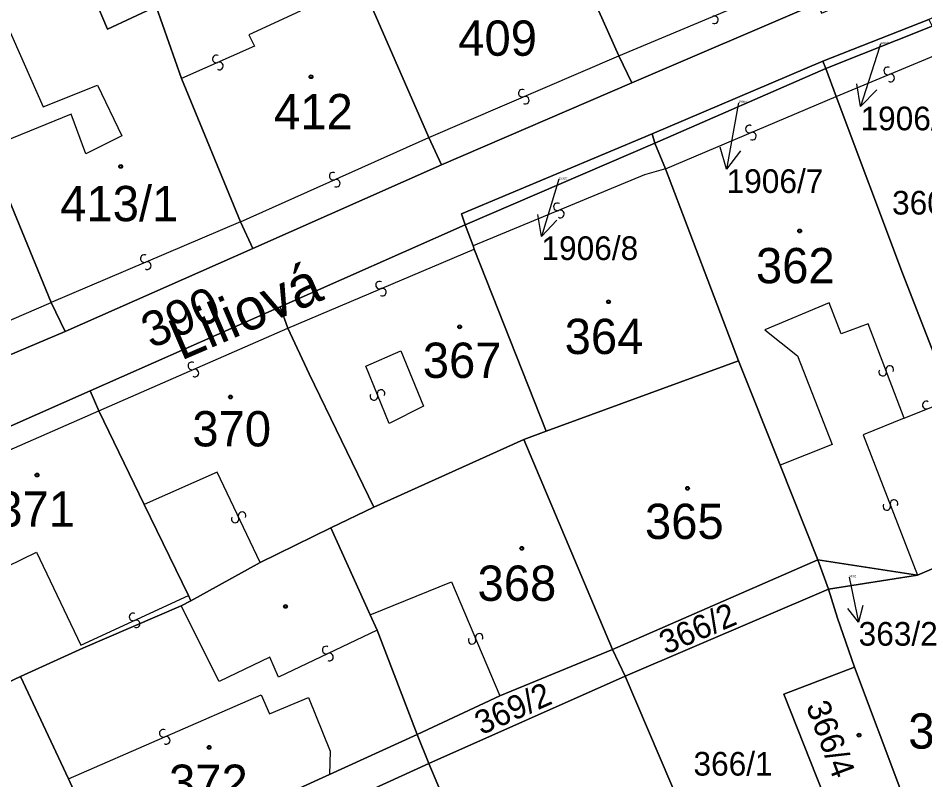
# Model space of a CAD drawing. Extents: x -598233 to -596890, y -1157848 to -1156431.
# Drawn here: x -597270.02 to -597226.34, y -1157526.17 to -1157489.47 of the extents above; entities that cross this region are included whole.
import ezdxf

# ---------------------------------------------------------------- set-up
doc = ezdxf.new("R2010")
doc.units = 0
for name, color, linetype in [('Level 1', 7, 'Continuous'), ('Level 11', 7, 'Continuous'), ('Level 13', 7, 'Continuous'), ('Level 3', 7, 'Continuous'), ('Level 4', 7, 'Continuous'), ('Level 5', 7, 'Continuous'), ('Level 57', 7, 'Continuous'), ('Level 60', 7, 'Continuous')]:
    doc.layers.add(name, color=color, linetype=linetype)

msp = doc.modelspace()

# ---------------------------------------------------------------- linework, layer by layer
at = {"layer": 'Level 1'}
for points in [[(-597268.85, -1157482.6), (-597265.71, -1157490), (-597263.37, -1157488.91)], [(-597244.31, -1157484.05), (-597241.08, -1157491.29)], [(-597253.48, -1157487.78), (-597250.23, -1157495.21)], [(-597231.5, -1157488.75), (-597240.46, -1157492.58)], [(-597262.15, -1157492.37), (-597263.37, -1157488.91)], [(-597226.15, -1157489.54), (-597231.25, -1157491.54)], [(-597225.99, -1157489.86), (-597231.11, -1157491.89)], [(-597241.08, -1157491.29), (-597240.46, -1157492.58)], [(-597231.25, -1157491.54), (-597239.48, -1157495.04)], [(-597231.25, -1157491.54), (-597231.11, -1157491.89)], [(-597231.11, -1157491.89), (-597239.34, -1157495.49)], [(-597231.11, -1157491.89), (-597230.61, -1157493.24)], [(-597259.31, -1157499.28), (-597262.15, -1157492.37)], [(-597240.46, -1157492.58), (-597249.62, -1157496.54)], [(-597230.61, -1157493.24), (-597227.41, -1157501.75), (-597225.11, -1157507.69)], [(-597250.23, -1157495.21), (-597249.62, -1157496.54)], [(-597248.48, -1157499.42), (-597248.66, -1157498.9), (-597239.48, -1157495.04)], [(-597239.48, -1157495.04), (-597239.34, -1157495.49)], [(-597271.5, -1157495.73), (-597268.43, -1157503.16)], [(-597239.34, -1157495.49), (-597248.48, -1157499.42)], [(-597239.34, -1157495.49), (-597238.83, -1157496.73)], [(-597249.62, -1157496.54), (-597258.71, -1157500.57)], [(-597238.83, -1157496.73), (-597235.31, -1157505.97)], [(-597258.71, -1157500.57), (-597259.31, -1157499.28)], [(-597248.48, -1157499.42), (-597257.4, -1157503.38)], [(-597248.1, -1157500.44), (-597248.48, -1157499.42)], [(-597258.71, -1157500.57), (-597267.76, -1157504.57)], [(-597248.05, -1157500.59), (-597248.1, -1157500.44)], [(-597244.58, -1157509.36), (-597248.05, -1157500.59)], [(-597268.43, -1157503.16), (-597267.76, -1157504.57)], [(-597266.55, -1157507.43), (-597257.4, -1157503.38)], [(-597257.4, -1157503.38), (-597257.02, -1157504.4)], [(-597257.02, -1157504.4), (-597256, -1157506.6), (-597252.89, -1157513.02)], [(-597267.76, -1157504.57), (-597282.78, -1157510.92)], [(-597244.58, -1157509.36), (-597235.31, -1157505.97)], [(-597235.31, -1157505.97), (-597233.31, -1157511.01)], [(-597275.31, -1157511.29), (-597266.55, -1157507.43)], [(-597266.55, -1157507.43), (-597266.14, -1157508.38)], [(-597266.14, -1157508.38), (-597263.95, -1157512.9)], [(-597245.66, -1157509.77), (-597244.58, -1157509.36)], [(-597252.89, -1157513.02), (-597245.66, -1157509.77)], [(-597241.38, -1157519.88), (-597245.66, -1157509.77)], [(-597233.31, -1157511.01), (-597231.5, -1157515.56)], [(-597263.95, -1157512.9), (-597261.82, -1157517.28)], [(-597252.89, -1157513.02), (-597254.95, -1157514.02)], [(-597258.36, -1157515.7), (-597254.95, -1157514.02)], [(-597254.95, -1157514.02), (-597253.06, -1157518.22)], [(-597222.48, -1157514.5), (-597226.69, -1157516.3)], [(-597261.7, -1157517.54), (-597258.36, -1157515.7)], [(-597231.5, -1157515.56), (-597241.38, -1157519.88)], [(-597231.5, -1157515.56), (-597230.98, -1157516.98)], [(-597226.69, -1157516.3), (-597231.5, -1157515.56)], [(-597226.69, -1157516.3), (-597230.98, -1157516.98)], [(-597240.77, -1157521.17), (-597230.98, -1157516.98)], [(-597229.73, -1157520.73), (-597230.55, -1157518.38), (-597230.98, -1157516.98)], [(-597261.7, -1157517.54), (-597262.16, -1157517.78)], [(-597261.82, -1157517.28), (-597261.7, -1157517.54)], [(-597262.16, -1157517.78), (-597266.91, -1157519.82), (-597269.91, -1157521.19)], [(-597253.06, -1157518.22), (-597252.73, -1157518.95)], [(-597252.73, -1157518.95), (-597250.8, -1157523.98)], [(-597241.38, -1157519.88), (-597246.82, -1157522.11)], [(-597240.77, -1157521.17), (-597241.38, -1157519.88)], [(-597229.73, -1157520.73), (-597233.14, -1157522.04), (-597230.9, -1157527.68), (-597227.49, -1157526.68)], [(-597229.73, -1157520.73), (-597227.49, -1157526.68)], [(-597269.91, -1157521.19), (-597270.52, -1157521.47)], [(-597267.6, -1157526.11), (-597269.91, -1157521.19)], [(-597250.23, -1157525.37), (-597240.77, -1157521.17)], [(-597236.37, -1157531.48), (-597240.77, -1157521.17)], [(-597246.82, -1157522.11), (-597250.8, -1157523.98)], [(-597250.8, -1157523.98), (-597255.02, -1157525.9)], [(-597250.8, -1157523.98), (-597250.23, -1157525.37)], [(-597250.23, -1157525.37), (-597264.87, -1157532.05)], [(-597250.23, -1157525.37), (-597245.9, -1157535.66)], [(-597255.02, -1157525.9), (-597265.53, -1157530.69)], [(-597265.53, -1157530.69), (-597267.6, -1157526.11)]]:
    msp.add_lwpolyline(points, dxfattribs=at)
at = {"layer": 'Level 13'}
for centre, start, end in [((-597236.479, -1157489.55), 240.0202, 112.6102), ((-597260.474, -1157491.431), 60.9843, 293.5743), ((-597260.327, -1157491.769), 241.1988, 113.2968), ((-597228.129, -1157492.009), 59.8886, 291.9866), ((-597227.99, -1157492.35), 239.6742, 112.2642), ((-597245.731, -1157493.08), 60.5638, 292.6618), ((-597245.588, -1157493.42), 240.3493, 112.9393), ((-597234.791, -1157494.81), 60.3776, 292.4756), ((-597234.649, -1157495.15), 240.1631, 112.7531), ((-597254.844, -1157497.081), 61.5165, 293.6145), ((-597254.695, -1157497.418), 241.302, 113.892), ((-597244.04, -1157498.56), 59.7092, 292.2992), ((-597243.901, -1157498.901), 239.9236, 112.0216), ((-597263.941, -1157501.05), 60.2051, 292.7951), ((-597263.799, -1157501.39), 240.4195, 112.5175), ((-597252.611, -1157502.33), 60.3861, 292.484), ((-597252.469, -1157502.67), 240.1716, 112.7616), ((-597261.652, -1157506.22), 60.9494, 293.0474), ((-597228.028, -1157506.395), 328.086, 200.676), ((-597261.507, -1157506.559), 240.7349, 113.3249), ((-597228.373, -1157506.524), 148.3005, 20.3985), ((-597252.539, -1157507.551), 329.4965, 202.0865), ((-597252.881, -1157507.689), 149.7109, 21.8089), ((-597226.268, -1157508.108), 59.4348, 291.5328), ((-597227.827, -1157512.855), 328.5578, 200.6558), ((-597228.172, -1157512.986), 148.3433, 20.9333), ((-597259.567, -1157513.598), 152.7697, 24.8677), ((-597259.233, -1157513.442), 332.5553, 205.1453), ((-597264.486, -1157518.312), 62.1409, 294.2389), ((-597264.334, -1157518.647), 241.9264, 114.5164), ((-597248.15, -1157519.441), 150.0665, 22.6565), ((-597247.809, -1157519.3), 330.281, 202.379), ((-597255.178, -1157519.913), 62.6029, 295.1929), ((-597255.022, -1157520.247), 242.8173, 114.9153), ((-597263.032, -1157523.92), 60.8758, 292.9738), ((-597262.887, -1157524.259), 240.6614, 113.2514)]:
    msp.add_arc(centre, 0.184, start, end, dxfattribs=at)
at = {"layer": 'Level 3'}
for points in [[(-597270.63, -1157478.58), (-597274.74, -1157480.34), (-597268.81, -1157493.74), (-597266.2, -1157492.69), (-597265.03, -1157495.14), (-597266.76, -1157496), (-597267.47, -1157494.1), (-597271.5, -1157495.73)], [(-597257.81, -1157486.25), (-597256.43, -1157489.13), (-597258.9, -1157490.27), (-597258.64, -1157490.82), (-597262.15, -1157492.37)], [(-597241.08, -1157491.29), (-597232.02, -1157487.47)], [(-597250.23, -1157495.21), (-597241.08, -1157491.29)], [(-597230.61, -1157493.24), (-597225.52, -1157491.13)], [(-597238.83, -1157496.73), (-597230.61, -1157493.24)], [(-597274.74, -1157494.37), (-597282.18, -1157497.48), (-597280.84, -1157500.56), (-597280.54, -1157500.44), (-597277.7, -1157507.16), (-597268.43, -1157503.16)], [(-597259.31, -1157499.28), (-597250.23, -1157495.21)], [(-597238.83, -1157496.73), (-597239.84, -1157497.01), (-597248.1, -1157500.44)], [(-597259.31, -1157499.28), (-597268.43, -1157503.16)], [(-597257.02, -1157504.4), (-597248.05, -1157500.59)], [(-597227.33, -1157508.74), (-597229.07, -1157504.19), (-597230.37, -1157504.67), (-597230.95, -1157503.19), (-597234.05, -1157504.48), (-597232.48, -1157505.73), (-597230.81, -1157510), (-597233.31, -1157511.01)], [(-597266.14, -1157508.38), (-597257.02, -1157504.4)], [(-597252.14, -1157508.99), (-597253.27, -1157506.24), (-597251.58, -1157505.49), (-597250.49, -1157508.16), (-597252.14, -1157508.99)], [(-597227.33, -1157508.74), (-597225.06, -1157507.82)], [(-597274.93, -1157512.24), (-597266.14, -1157508.38)], [(-597227.33, -1157508.74), (-597229.31, -1157509.54), (-597226.69, -1157516.3)], [(-597258.36, -1157515.7), (-597260.43, -1157511.34), (-597263.95, -1157512.9)], [(-597272.7, -1157516.93), (-597269.13, -1157515.19), (-597267, -1157519.67), (-597261.82, -1157517.28)], [(-597253.06, -1157518.22), (-597249.14, -1157516.62), (-597246.82, -1157522.11)], [(-597252.73, -1157518.95), (-597257.48, -1157521.21), (-597257.9, -1157520.25), (-597260.33, -1157521.43), (-597262.16, -1157517.78)], [(-597267.6, -1157526.11), (-597258.31, -1157522.07), (-597257.91, -1157522.99), (-597256.04, -1157522.19), (-597254.99, -1157524.78), (-597255.02, -1157525.9)]]:
    msp.add_lwpolyline(points, dxfattribs=at)
at = {"layer": 'Level 5'}
for centre, radius in [((-597255.91, -1157492.29), 0.09), ((-597255.91, -1157492.29), 0.0521), ((-597265.08, -1157496.61), 0.09), ((-597265.08, -1157496.61), 0.0521), ((-597232.37, -1157499.72), 0.09), ((-597232.37, -1157499.72), 0.0521), ((-597241.58, -1157503.13), 0.09), ((-597241.58, -1157503.13), 0.0521), ((-597248.75, -1157504.34), 0.09), ((-597248.75, -1157504.34), 0.0521), ((-597259.79, -1157507.72), 0.09), ((-597259.79, -1157507.72), 0.0521), ((-597269.11, -1157511.48), 0.09), ((-597269.11, -1157511.48), 0.0521), ((-597237.77, -1157512.12), 0.09), ((-597237.77, -1157512.12), 0.0521), ((-597245.76, -1157515.01), 0.09), ((-597245.76, -1157515.01), 0.0521), ((-597257.14, -1157517.81), 0.09), ((-597257.14, -1157517.81), 0.0521), ((-597229.51, -1157524.01), 0.09), ((-597229.51, -1157524.01), 0.0521), ((-597260.82, -1157524.6), 0.09), ((-597260.82, -1157524.6), 0.0521)]:
    msp.add_circle(centre, radius, dxfattribs=at)
at = {"layer": 'Level 57'}
for p, q in [((-597228.531, -1157490.871), (-597229.44, -1157493.73)), ((-597228.48, -1157490.71), (-597228.531, -1157490.871)), ((-597235.31, -1157493.54), (-597235.357, -1157493.798)), ((-597235.357, -1157493.798), (-597235.89, -1157496.75)), ((-597243.97, -1157497.23), (-597244.81, -1157499.98)), ((-597229.99, -1157516.4), (-597229.53, -1157518.56))]:
    msp.add_line(p, q, dxfattribs=at)
for points in [[(-597228.66, -1157492.928), (-597229.44, -1157493.73), (-597229.613, -1157492.626)], [(-597235.221, -1157495.855), (-597235.89, -1157496.75), (-597236.205, -1157495.677)], [(-597244.072, -1157499.203), (-597244.81, -1157499.98), (-597244.988, -1157498.923)], [(-597229.323, -1157517.763), (-597229.53, -1157518.56), (-597230.043, -1157517.917)]]:
    msp.add_lwpolyline(points, dxfattribs=at)
at = {"layer": 'Level 60'}
for points in [[(-597282.78, -1157510.92), (-597267.76, -1157504.57), (-597258.71, -1157500.57), (-597249.62, -1157496.54), (-597240.46, -1157492.58), (-597231.5, -1157488.75), (-597231.32, -1157489.23), (-597222.21, -1157485.39), (-597212.78, -1157481.41), (-597193.99, -1157474.56), (-597185.11, -1157471.38), (-597173, -1157467.1)], [(-597177.21, -1157471.08), (-597193.2, -1157476.66), (-597202.68, -1157480.14), (-597212.03, -1157483.8), (-597221.24, -1157487.45), (-597226.15, -1157489.54), (-597231.25, -1157491.54), (-597239.48, -1157495.04), (-597248.66, -1157498.9), (-597248.48, -1157499.42), (-597257.4, -1157503.38), (-597266.55, -1157507.43), (-597275.31, -1157511.29)]]:
    msp.add_lwpolyline(points, dxfattribs=at)
for points in [[(-597270.63, -1157478.58), (-597271.88, -1157475.05), (-597264.04, -1157471.7), (-597263.77, -1157472.19), (-597262.41, -1157471.57), (-597259.76, -1157478.4), (-597257.79, -1157482.94), (-597256.85, -1157485.81), (-597257.81, -1157486.25), (-597260.24, -1157487.36), (-597263.37, -1157488.91), (-597265.71, -1157490), (-597268.85, -1157482.6)], [(-597277.8, -1157486.78), (-597281.49, -1157479.06), (-597271.88, -1157475.05), (-597270.63, -1157478.58), (-597268.85, -1157482.6), (-597265.71, -1157490), (-597263.37, -1157488.91), (-597262.15, -1157492.37), (-597259.31, -1157499.28), (-597258.71, -1157500.57), (-597267.76, -1157504.57), (-597268.43, -1157503.16), (-597271.5, -1157495.73), (-597272.44, -1157493.44), (-597274.74, -1157494.37), (-597276.47, -1157490.08)], [(-597245.49, -1157481.23), (-597245.56, -1157481.06), (-597243.88, -1157480.33), (-597241.55, -1157479.31), (-597238.96, -1157478.17), (-597236.52, -1157477), (-597235.98, -1157478.27), (-597234.74, -1157481.03), (-597232.02, -1157487.47), (-597231.5, -1157488.75), (-597240.46, -1157492.58), (-597241.08, -1157491.29), (-597244.31, -1157484.05)], [(-597253.48, -1157487.78), (-597254.65, -1157484.92), (-597247.99, -1157482.25), (-597245.49, -1157481.23), (-597244.31, -1157484.05), (-597241.08, -1157491.29), (-597240.46, -1157492.58), (-597249.62, -1157496.54), (-597250.23, -1157495.21)], [(-597263.37, -1157488.91), (-597260.24, -1157487.36), (-597257.81, -1157486.25), (-597256.85, -1157485.81), (-597254.65, -1157484.92), (-597253.48, -1157487.78), (-597250.23, -1157495.21), (-597249.62, -1157496.54), (-597258.71, -1157500.57), (-597259.31, -1157499.28), (-597262.15, -1157492.37)], [(-597231.25, -1157491.54), (-597226.15, -1157489.54), (-597225.99, -1157489.86), (-597231.11, -1157491.89)], [(-597286.78, -1157505.77), (-597287.77, -1157503.36), (-597288.62, -1157500.66), (-597287.26, -1157500.03), (-597283.52, -1157498.6), (-597285.05, -1157494.49), (-597276.47, -1157490.08), (-597274.74, -1157494.37), (-597272.44, -1157493.44), (-597271.5, -1157495.73), (-597268.43, -1157503.16), (-597267.76, -1157504.57), (-597282.78, -1157510.92), (-597285.26, -1157505.18)], [(-597230.61, -1157493.24), (-597231.11, -1157491.89), (-597225.99, -1157489.86), (-597225.52, -1157491.13), (-597222.26, -1157499.56), (-597216.44, -1157512.85), (-597218.43, -1157513.11), (-597222.48, -1157514.5), (-597225.06, -1157507.82), (-597225.11, -1157507.69), (-597227.41, -1157501.75)], [(-597239.48, -1157495.04), (-597231.25, -1157491.54), (-597231.11, -1157491.89), (-597239.34, -1157495.49)], [(-597231.11, -1157491.89), (-597230.61, -1157493.24), (-597227.41, -1157501.75), (-597225.11, -1157507.69), (-597225.06, -1157507.82), (-597222.48, -1157514.5), (-597226.69, -1157516.3), (-597231.5, -1157515.56), (-597233.31, -1157511.01), (-597235.31, -1157505.97), (-597238.83, -1157496.73), (-597239.34, -1157495.49)], [(-597239.48, -1157495.04), (-597239.34, -1157495.49), (-597248.48, -1157499.42), (-597248.66, -1157498.9)], [(-597238.83, -1157496.73), (-597235.31, -1157505.97), (-597244.58, -1157509.36), (-597248.05, -1157500.59), (-597248.1, -1157500.44), (-597248.48, -1157499.42), (-597239.34, -1157495.49)], [(-597244.58, -1157509.36), (-597245.66, -1157509.77), (-597252.89, -1157513.02), (-597256, -1157506.6), (-597257.02, -1157504.4), (-597257.4, -1157503.38), (-597248.48, -1157499.42), (-597248.1, -1157500.44), (-597248.05, -1157500.59)], [(-597257.4, -1157503.38), (-597257.02, -1157504.4), (-597256, -1157506.6), (-597252.89, -1157513.02), (-597254.95, -1157514.02), (-597258.36, -1157515.7), (-597261.7, -1157517.54), (-597261.82, -1157517.28), (-597263.95, -1157512.9), (-597266.14, -1157508.38), (-597266.55, -1157507.43)], [(-597235.31, -1157505.97), (-597233.31, -1157511.01), (-597231.5, -1157515.56), (-597241.38, -1157519.88), (-597245.66, -1157509.77), (-597244.58, -1157509.36)], [(-597269.91, -1157521.19), (-597270.52, -1157521.47), (-597272.7, -1157516.93), (-597274.93, -1157512.24), (-597275.31, -1157511.29), (-597266.55, -1157507.43), (-597266.14, -1157508.38), (-597263.95, -1157512.9), (-597261.82, -1157517.28), (-597261.7, -1157517.54), (-597262.16, -1157517.78), (-597266.91, -1157519.82)], [(-597245.66, -1157509.77), (-597241.38, -1157519.88), (-597246.82, -1157522.11), (-597250.8, -1157523.98), (-597252.73, -1157518.95), (-597253.06, -1157518.22), (-597254.95, -1157514.02), (-597252.89, -1157513.02)], [(-597254.95, -1157514.02), (-597253.06, -1157518.22), (-597252.73, -1157518.95), (-597250.8, -1157523.98), (-597255.02, -1157525.9), (-597265.53, -1157530.69), (-597267.6, -1157526.11), (-597269.91, -1157521.19), (-597266.91, -1157519.82), (-597262.16, -1157517.78), (-597261.7, -1157517.54), (-597258.36, -1157515.7)], [(-597222.48, -1157514.5), (-597218.81, -1157525.05), (-597225.75, -1157527.44), (-597226.97, -1157527.79), (-597227.49, -1157526.68), (-597229.73, -1157520.73), (-597230.55, -1157518.38), (-597230.98, -1157516.98), (-597226.69, -1157516.3)], [(-597230.98, -1157516.98), (-597240.77, -1157521.17), (-597241.38, -1157519.88), (-597231.5, -1157515.56)], [(-597226.69, -1157516.3), (-597230.98, -1157516.98), (-597231.5, -1157515.56)], [(-597227.49, -1157526.68), (-597226.97, -1157527.79), (-597236.37, -1157531.48), (-597240.77, -1157521.17), (-597230.98, -1157516.98), (-597230.55, -1157518.38), (-597229.73, -1157520.73), (-597233.14, -1157522.04), (-597230.9, -1157527.68)], [(-597240.77, -1157521.17), (-597250.23, -1157525.37), (-597250.8, -1157523.98), (-597246.82, -1157522.11), (-597241.38, -1157519.88)], [(-597229.73, -1157520.73), (-597227.49, -1157526.68), (-597230.9, -1157527.68), (-597233.14, -1157522.04)], [(-597267.6, -1157526.11), (-597265.53, -1157530.69), (-597278.6, -1157536.78), (-597279.2, -1157537.04), (-597282.73, -1157529.29), (-597282.81, -1157529.12), (-597283.62, -1157527.21), (-597278.19, -1157524.95), (-597276.47, -1157524.11), (-597274.53, -1157523.25), (-597270.52, -1157521.47), (-597269.91, -1157521.19)], [(-597240.77, -1157521.17), (-597236.37, -1157531.48), (-597245.9, -1157535.66), (-597250.23, -1157525.37)], [(-597255.02, -1157525.9), (-597250.8, -1157523.98), (-597250.23, -1157525.37), (-597264.87, -1157532.05), (-597265.53, -1157530.69)], [(-597250.23, -1157525.37), (-597245.9, -1157535.66), (-597260.14, -1157542.11), (-597260.47, -1157541.33), (-597263.63, -1157534.68), (-597264.87, -1157532.05)]]:
    msp.add_lwpolyline(points, close=True, dxfattribs=at)

# ---------------------------------------------------------------- texts
at = {"layer": 'Level 11'}
msp.add_text('Liliová', height=2, rotation=23.2154, dxfattribs=at).set_placement((-597262.182, -1157505.984))
at = {"layer": 'Level 4'}
for s, height, p in [('409', 1.7, (-597248.818, -1157491.28)), ('1906/6', 0.1, (-597228.48, -1157490.71)), ('412', 1.7, (-597257.692, -1157494.82)), ('1906/7', 0.1, (-597235.31, -1157493.54)), ('413/1', 1.7, (-597267.992, -1157499.25)), ('1906/8', 0.1, (-597243.97, -1157497.23)), ('360/2', 1.14, (-597227.92, -1157498.93)), ('362', 1.7, (-597234.476, -1157502.24)), ('364', 1.7, (-597243.691, -1157505.65)), ('367', 1.7, (-597250.526, -1157506.8)), ('370', 1.7, (-597261.629, -1157510.1)), ('371', 1.7, (-597271.078, -1157513.97)), ('365', 1.7, (-597239.822, -1157514.56)), ('368', 1.7, (-597247.889, -1157517.54)), ('363/2', 0.1, (-597229.99, -1157516.4)), ('363/1', 1.7, (-597227.136, -1157524.66)), ('366/1', 1.14, (-597237.486, -1157525.96)), ('372', 1.7, (-597262.751, -1157527.13))]:
    msp.add_text(s, height=height, dxfattribs=at).set_placement(p)
for s, height, rotation, p in [('390', 1.7, 23.5349, (-597263.603, -1157505.409)), ('366/2', 1.14, 23.1703, (-597238.823, -1157520.142)), ('369/2', 1.14, 23.94, (-597247.702, -1157524.018)), ('366/4', 1.14, 290.6299, (-597232.08, -1157522.602))]:
    msp.add_text(s, height=height, rotation=rotation, dxfattribs=at).set_placement(p)
at = {"layer": 'Level 57'}
for s, p in [('1906/6', (-597229.44, -1157494.87)), ('1906/7', (-597235.89, -1157497.89)), ('1906/8', (-597244.81, -1157501.12)), ('363/2', (-597229.53, -1157519.7))]:
    msp.add_text(s, height=1.14, dxfattribs=at).set_placement(p)

doc.saveas('drawing.dxf')
